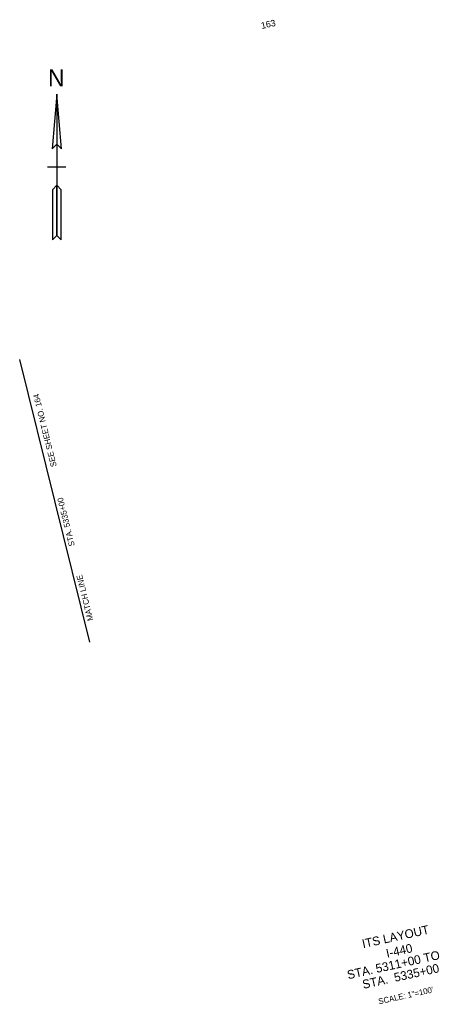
# Model space of a CAD drawing. Extents: x -200 to 1748284, y -325 to 653558.
# Drawn here: x 1747420 to 1748284, y 651530 to 653558 of the extents above; entities that cross this region are included whole.
import ezdxf

# ---------------------------------------------------------------- set-up
doc = ezdxf.new("R2010")
doc.units = 0
for name, color, linetype in [('DESIGN - CENTERLINE - Proposed Text', 7, 'Continuous'), ('DESIGN - SCRATCH - User 1', 7, 'Continuous'), ('DESIGN - SHEET - Corner Text', 7, 'Continuous'), ('ITS - CONST TEXT', 7, 'Continuous'), ('ITS - EXISITING WEATHER STATION', 7, 'Continuous'), ('ITS - EXISTING COMM CABLE', 7, 'Continuous'), ('ITS - EXISTING HAR', 7, 'Continuous')]:
    doc.layers.add(name, color=color, linetype=linetype)

msp = doc.modelspace()

# ---------------------------------------------------------------- linework, layer by layer
at = {"layer": 'DESIGN - CENTERLINE - Proposed Text'}
for p, q in [((1747496.4, 653254.3), (1747477.5, 653254.3)), ((1747515.3, 653254.3), (1747496.4, 653254.3))]:
    msp.add_line(p, q, dxfattribs=at)
msp.add_lwpolyline([(1747496.4, 653404.3), (1747486.6, 653291.7), (1747496.4, 653301.5), (1747506.2, 653291.7), (1747496.4, 653404.3), (1747496.4, 653113.4), (1747505.5, 653104.3), (1747505.5, 653207.8), (1747496.4, 653216.9), (1747487.3, 653207.8), (1747487.3, 653104.3), (1747496.4, 653113.4)], dxfattribs=at)
for points in [[(1747496.4, 653301.5), (1747506.2, 653291.7), (1747496.4, 653404.3)], [(1747487.3, 653104.3), (1747496.4, 653113.4), (1747496.4, 653216.9), (1747487.3, 653207.8)]]:
    msp.add_lwpolyline(points, close=True, dxfattribs=at)
at = {"layer": 'DESIGN - SCRATCH - User 1'}
for p, q in [((1748219.3, 651630.6), (1748219.3, 651630.6)), ((1748219.3, 651630.6), (1748219.3, 651630.6)), ((1748226, 651615.3), (1748226, 651615.3))]:
    msp.add_line(p, q, dxfattribs=at)
at = {"layer": 'ITS - EXISITING WEATHER STATION'}
msp.add_line((1748219.1, 651630.7), (1748219.1, 651630.7), dxfattribs=at)
msp.add_line((1748219.1, 651630.7), (1748219.1, 651630.7), dxfattribs=at)
at = {"layer": 'ITS - EXISTING COMM CABLE'}
msp.add_line((1747564.5, 652275.7), (1747420, 652858), dxfattribs=at)

# ---------------------------------------------------------------- texts
at = {"layer": 'DESIGN - CENTERLINE - Proposed Text'}
msp.add_text('N', height=35.4, dxfattribs=at).set_placement((1747478.3, 653420.4))
at = {"layer": 'DESIGN - SHEET - Corner Text'}
msp.add_text('163', height=13.5, rotation=12.4282, dxfattribs=at).set_placement((1747918.6, 653538.8))
at = {"layer": 'ITS - CONST TEXT'}
msp.add_text('SCALE: 1"=100\'', height=12, rotation=12.4283, dxfattribs=at).set_placement((1748160.1, 651529.5))
at = {"layer": 'ITS - EXISTING COMM CABLE'}
for s, p in [('SEE SHEET NO. 164 ', (1747496.3, 652638.4)), ('STA. 5335+00', (1747533.6, 652474.7)), ('MATCH LINE', (1747571.7, 652321.3))]:
    msp.add_text(s, height=12, rotation=103.9321, dxfattribs=at).set_placement(p)
at = {"layer": 'ITS - EXISTING HAR'}
for s, p in [('ITS LAYOUT', (1748127.3, 651645.2)), ('I-440', (1748176.7, 651625.5)), ('STA. 5311+00 TO', (1748096.5, 651581.2)), ('STA.  5335+00', (1748127.8, 651561.4))]:
    msp.add_text(s, height=18, rotation=12.4283, dxfattribs=at).set_placement(p)

doc.saveas('drawing.dxf')
